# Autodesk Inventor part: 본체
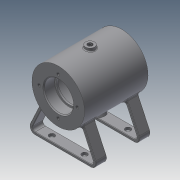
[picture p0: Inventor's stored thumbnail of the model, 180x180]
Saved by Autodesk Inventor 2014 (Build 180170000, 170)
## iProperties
Created: 2021-12
Part Number: 본체
Material: 일반
Document SubType Name: Modeling
Designer: dg
Density: 1 g/cm^3
Appearance: 기본값
Author: dg
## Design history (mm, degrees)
sketch "스케치1"
  geometry: L1 (-35, 0)-(35, 0); L2 (-34, 16)-(-23.3, 16); L3 (-23, 15.7)-(-23, 14); L4 (-23, 14)-(-21, 14); L5 (-21, 14)-(-21, 18); L6 (-18, 21)-(18, 21); L7 (21, 18)-(21, 14); L8 (21, 14)-(23, 14); L9 (23, 14)-(23, 15.7); L10 (23.3, 16)-(34, 16); L11 (35, 17)-(35, 29); L12 (35, 29)-(-35, 29); L13 (-35, 29)-(-35, 17); L14 (35, 17)-(34, 16); L15 (-35, 17)-(-34, 16); A1 r 3 centre (-18, 18) between (-18, 21) and (-21, 18); A2 r 3 centre (18, 18) between (21, 18) and (18, 21); A3 r 0.3 centre (-23.3, 15.7) between (-23, 15.7) and (-23.3, 16); A4 r 0.3 centre (23.3, 15.7) between (23.3, 16) and (23, 15.7); 8 further points
  constraints: 30 end point, 12 point on line, 9 parallel, 8 point on circle, 8 tangent, 4 centre point, 3 collinear, 2 equal radius, 2 horizontal alignment, 2 vertical alignment, 1 coincident, 1 horizontal, 1 midpoint, 1 perpendicular, 1 vertical
  dimensions: "d0" = 70 distance of L1.start L1.end; "d1" = 42 distance of point (-21, 21) point (21, 21); "d2" = 12 distance of point (23, 16) point (35, 16); "d3" = 28 diameter of L7.end L1; "d4" = 32 diameter of L10 L1; "d5" = 42 diameter of L6 L1; "d6" = 58 diameter of L12 L1; "d7" = 3 radius of A1; "d8" = 0.3 radius of A3; "d9" = 1 distance of L11.start point (35, 16); "d10" = 1 distance of L10.end point (35, 16) (= d9); "d11" = 1 distance of L13.end point (-35, 16) (= d9); "d12" = 1 distance of L2.start point (-35, 16) (= d11)
revolve "회전1" sketch "스케치1" stored, may be unused: angle "d13" = 90 deg
sketch "스케치2"
  geometry: C1 r 17 at (0, 0) reference; C2 r 29 at (0, 0) reference; A1 r 21 centre (0, 0) between (0, 21) and (-21, 0); 2 further points
  constraints: 4 point on circle, 2 horizontal alignment, 2 vertical alignment, 1 centre point, 1 coincident
  dimensions: "d14" = 42 diameter of A1
hole "구멍1" sketch "스케치2" at (0, 21), (-21, 0), (0, -21), (21, 0) diameter "d15" = 3.242; stored, may be unused: countersink angle "d19" = 90 deg, drill point angle "d21" = 118 deg; dims "d16" = 8, "d17" = 4, "d18" = 2, "d20" = 10
node "작업 평면1"
sketch "스케치3"
  geometry: C1 r 5 at (0, 0); C2 r 1.5 at (0, 0); 2 further points
  constraints: 3 coincident, 2 centre point
  dimensions: "d23" = 10 diameter of C1; "d24" = 3 diameter of C2
extrude "돌출1" join sketch "스케치3" stored distance "d25" = 10; taper "d26" = 0 deg
hole "구멍2" sketch "스케치3" diameter "d27" = 5.188; stored, may be unused: countersink angle "d31" = 90 deg, drill point angle "d33" = 118 deg; dims "d28" = 6, "d29" = 4, "d30" = 2, "d32" = 8
extrude "돌출2" cut sketch "스케치3" stored distance "d34" = 10; taper "d35" = 0 deg
node "작업 평면2"
sketch "스케치4"
  geometry: L1 (5, 32)-(5, 28.566) reference; L2 (-5, 28.566)-(-5, 32) reference; L3 (-5, 32)-(-2.594, 32) reference; L4 (-2.594, 32)-(-2.594, 24) reference; L5 (-2.594, 24)-(-1.5, 23.343) reference; L6 (-1.5, 23.343)-(-1.5, 20.946) reference; L7 (1.5, 20.946)-(1.5, 23.343) reference; L8 (1.5, 23.343)-(2.594, 24) reference; L9 (2.594, 24)-(2.594, 32) reference; L10 (2.594, 32)-(5, 32) reference; L11 (0, 0)-(0, -29); L12 (0, 0)-(10.945, -30.07); A1 r 29 centre (0, 0) between (-5, 28.566) and (5, 28.566) reference; A2 r 21 centre (0, 0) between (-1.5, 20.946) and (1.5, 20.946) reference; 1 further point
  constraints: 4 end point, 1 point on circle
  dimensions: "d37" = 20 deg angle of L12 L11; "d38" = 32 distance of L11.start L12.end
  node "절단 모서리 투영1"
node "작업 평면3"
sketch "스케치5"
  geometry: C1 r 6 at (0, 0); 2 further points
  constraints: 2 coincident, 1 centre point
  dimensions: "d39" = 12 diameter of C1
extrude "돌출3" join sketch "스케치5" stored distance "d40" = 10; taper "d41" = 0 deg
hole "구멍3" sketch "스케치5" diameter "d42" = 5.188; stored, may be unused: countersink angle "d46" = 90 deg, drill point angle "d48" = 118 deg; dims "d43" = 6, "d44" = 4, "d45" = 2, "d47" = 8
node "작업 평면4"
sketch "스케치6"
  geometry: L1 (-22.743, -17.993)-(-40, -55); L2 (-40, -55)-(40, -55); L3 (40, -55)-(22.743, -17.993); L4 (20.574, -20.438)-(35.291, -52); L5 (35.291, -52)-(-35.291, -52); L6 (-35.291, -52)-(-20.574, -20.438); C1 r 16 at (0, 0) reference; A1 r 29 centre (0, 0) between (-22.743, -17.993) and (22.743, -17.993) reference; 1 further point
  constraints: 12 end point, 4 point on circle, 3 parallel, 1 equal length, 1 horizontal, 1 horizontal alignment
  dimensions: "d50" = 80 distance of L1.end L2.end; "d51" = 55 distance from line of L2 point (0, 0); "d52" = 65 deg angle of L2 L1; "d53" = 3 distance between parallel lines of L2 L5; "d54" = 3 distance between parallel lines of L3 L4; "d55" = 3 distance between parallel lines of L1 L6
extrude "돌출4" join sketch "스케치6" stored distance "d56" = 12; taper "d57" = 0 deg
fillet "모깎기1" dims "d58" = 6, "d59" = 3
fillet "모깎기2" dims "d60" = 0.5
fillet "모깎기3" dims "d61" = 3, "d62" = 1
sketch "스케치7"
  geometry: L1 (61.164, 48)-(0, 48) reference; L2 (0, 37)-(0, 48) reference; L3 (0, 37)-(61.164, 37) reference; L4 (61.164, 37)-(61.164, 48) reference; L5 (0, 0)-(61.164, 0) reference; L6 (61.164, -11)-(61.164, 0) reference; L7 (61.164, -11)-(0, -11) reference; L8 (0, -11)-(0, 0) reference; C1 r 3 at (12.582, 42.5); C2 r 3 at (48.582, 42.5); 2 further points
  constraints: 2 centre point, 2 horizontal alignment, 1 equal radius, 1 midpoint
  dimensions: "d63" = 36 distance of C2.centre C1.centre; "d64" = 6 diameter of C2; "d65" = 18 horizontal distance of point (30.582, 18.5) C1.centre
extrude "돌출5" cut sketch "스케치7" stored distance "d66" = 12; taper "d67" = 0 deg
node "작업 평면5"
sketch "스케치8"
  geometry: L1 (-35, -29)-(-35, 29) reference; 2 further points
  constraints: 2 coincident, 1 other
feature "엠보싱1" sketch "스케치8" dims "d0" = 70, "d1" = 42, "d2" = 12, "d3" = 28, "d4" = 32, "d5" = 42, "d6" = 58, "d7" = 3, "d8" = 0.3, "d9" = 1, "d10" = 1 (= d9), "d11" = 1 (= d9), "d12" = 1 (= d11), "d71" = 0.5, "d72" = 0
node "솔리드1"
mirror "대칭1"
mirror "대칭2"
mirror "대칭3"
node "절단 모서리 투영2"
node "절단 모서리 투영3"
other parameters: "d22" = 32, "d36" = -35, "d49" = -24, "d68" = -29
